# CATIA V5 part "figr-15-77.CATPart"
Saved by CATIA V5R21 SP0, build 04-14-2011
Part number: Part1
Bounding box of the stored display mesh (mm): x -59.264 to 75.079, y -54.323 to 58.486, z 0 to 41.762
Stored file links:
  D:\CATIA V5R21 E-RESOURCES\CATIA-V5R21\catia-v5r21-prt\c15-catia-v5r20-prt\c15-catia-v5r21-figr-15-69.CATPart
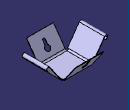
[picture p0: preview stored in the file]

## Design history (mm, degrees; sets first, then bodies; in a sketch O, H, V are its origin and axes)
SheetMetalParameters1: Thickness 1, BendRadius 5, KFactor 0.5 {= log(min(100,max(20*SheetMetalParameters1.BendRadius,SheetMetalParameters1.Thickness)/SheetMetalParameters1.Thickness))/log(100)/2}, ReliefRadialLength 1, ReliefAxialLength 2, MinimumBendRadius 0
Body1 (main body)
  Sketch1 on xy-plane, origin (0, 0, 0), H (1, 0, 0), V (0, 1, 0)
    line L1 (-24.5181, 30.1968) -> (40.3332, 30.1968)
    line L2 (40.3332, 30.1968) -> (40.3332, -26.0343)
    line L3 (40.3332, -26.0343) -> (-24.5181, -26.0343)
    line L4 (-24.5181, -26.0343) -> (-24.5181, 30.1968)
    horizontal: L1 H, L3 H
    vertical: L2 V, L4 V
  Wall1: Thickness 1, Profile Sketch1
  d_NewWallOnEdge1: NewWallOnEdge_Edge edge [face of Wall1 | face of Wall1], NewWallOnEdge_Length 40.2311, NewWallOnEdge_HeightLimitOffset 0, NewWallOnEdge_WidthOffset1 0, NewWallOnEdge_WidthOffset2 0, NewWallOnEdge_Angle 125, NewWallOnEdge_BendRadiusValue 5 {= SheetMetalParameters1.BendRadius}, NewWallOnEdge_BendTable SheetMetalParameters1, KFacteur 0.5 {= log(min(100,max(20*d_NewWallOnEdge1.Radius,SheetMetalParameters1.Thickness)/SheetMetalParameters1.Thickness))/log(100)/2}
  d_NewWallOnEdge2: NewWallOnEdge_Edge edge [face of Wall1 | face of Wall1], NewWallOnEdge_Length 40.2311, NewWallOnEdge_HeightLimitOffset 0, NewWallOnEdge_WidthOffset1 0, NewWallOnEdge_WidthOffset2 0, NewWallOnEdge_Angle 125, NewWallOnEdge_BendRadiusValue 5 {= SheetMetalParameters1.BendRadius}, NewWallOnEdge_BendTable SheetMetalParameters1, KFacteur 0.5 {= log(min(100,max(20*d_NewWallOnEdge2.Radius,SheetMetalParameters1.Thickness)/SheetMetalParameters1.Thickness))/log(100)/2}
  d_NewWallOnEdge3: NewWallOnEdge_Edge edge [face of Wall1 | face of Wall1], NewWallOnEdge_Length 40.2311, NewWallOnEdge_HeightLimitOffset 0, NewWallOnEdge_WidthOffset1 0, NewWallOnEdge_WidthOffset2 0, NewWallOnEdge_Angle 125, NewWallOnEdge_BendRadiusValue 5 {= SheetMetalParameters1.BendRadius}, NewWallOnEdge_BendTable SheetMetalParameters1, KFacteur 0.5 {= log(min(100,max(20*d_NewWallOnEdge3.Radius,SheetMetalParameters1.Thickness)/SheetMetalParameters1.Thickness))/log(100)/2}
  d_NewWallOnEdge4: NewWallOnEdge_Edge edge [face of Wall1 | face of Wall1], NewWallOnEdge_Length 40.2311, NewWallOnEdge_HeightLimitOffset 0, NewWallOnEdge_WidthOffset1 0, NewWallOnEdge_WidthOffset2 0, NewWallOnEdge_Angle 125, NewWallOnEdge_BendRadiusValue 5 {= SheetMetalParameters1.BendRadius}, NewWallOnEdge_BendTable SheetMetalParameters1, KFacteur 0.5 {= log(min(100,max(20*d_NewWallOnEdge4.Radius,SheetMetalParameters1.Thickness)/SheetMetalParameters1.Thickness))/log(100)/2}
  Sketch2 on face of d_NewWallOnEdge4, origin (0, -16.9994, -11.9031), H (-1, 0, 0), V (0, -0.5736, 0.8192)
    construction line L1 (-8.3417, 33.0355) -> (-8.3417, 47.6528)
    line L2 (-5.6402, 47.6528) -> (-5.6402, 38.4491)
    line L3 (-11.0431, 38.4491) -> (-11.0431, 47.6528)
    arc A1 centre (-8.3417, 33.0355) radius 6.0503 from (-5.6402, 38.4491) to (-11.0431, 38.4491) cw
    arc A2 centre (-8.3417, 47.6528) radius 2.7015 from (-11.0431, 47.6528) to (-5.6402, 47.6528) cw
    radius A1 = 6.0503
    radius A2 = 2.7015
    vertical: L1 V
    tangency: A2 L2, A2 L3
    parallelism: L2 L3, L2 L1
  CutOut1: Direction Sketch2, EndLimit through (limit type 3), Orientation false, Profile Sketch2, StartLimit through (limit type 2)
  Sketch3 on face of d_NewWallOnEdge2, origin (0, 19.7925, -13.8589), H (1, 0, 0), V (0, 0.5736, 0.8192)
    construction line L1 (6.0153, 41.1403) -> (6.0153, 57.8706)
    line L2 (8.7383, 57.8706) -> (8.7383, 46.3808)
    line L3 (3.2923, 46.3808) -> (3.2923, 57.8706)
    arc A1 centre (6.0153, 41.1403) radius 5.9058 from (8.7383, 46.3808) to (3.2923, 46.3808) cw
    arc A2 centre (6.0153, 57.8706) radius 2.723 from (3.2923, 57.8706) to (8.7383, 57.8706) cw
    radius A1 = 5.9058
    radius A2 = 2.723
    vertical: L1 V
    tangency: A2 L2, A2 L3
    parallelism: L2 L3, L2 L1
  CutOut2: Direction Sketch3, EndLimit through (limit type 3), Orientation true, Profile Sketch3, StartLimit through (limit type 2)
  Flange1: Angle 90, Length 5, Radius 3, KFacteur 0.444538 {= log(min(100,max(20*Flange1.Radius,SheetMetalParameters1.Thickness)/SheetMetalParameters1.Thickness))/log(100)/2}, Guide edge [face of d_NewWallOnEdge1 | face of d_NewWallOnEdge1]
  Flange2: Angle 90, Length 5, Radius 3, KFacteur 0.444538 {= log(min(100,max(20*Flange2.Radius,SheetMetalParameters1.Thickness)/SheetMetalParameters1.Thickness))/log(100)/2}, Guide edge [face of d_NewWallOnEdge3 | face of d_NewWallOnEdge3]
